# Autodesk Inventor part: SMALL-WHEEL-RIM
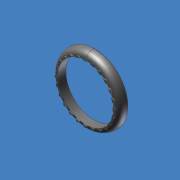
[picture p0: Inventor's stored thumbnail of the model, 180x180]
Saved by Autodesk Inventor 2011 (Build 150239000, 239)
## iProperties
Created: 2007-08
Part Number: SMALL-WHEEL-RIM
Material: ABS Plastic
Document SubType Name: Modeling
Density: 1.06 g/cm^3
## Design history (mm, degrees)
feature "Base1"
body "Solid1"
